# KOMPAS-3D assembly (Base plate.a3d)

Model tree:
1. X Axis
2. Y Axis
3. Z Axis
4. Origin
5. Linear Pattern:1  (labels: Instance ( 2, 1 );; Instance ( 3, 1 );; Instance ( 4, 1 );; Instance ( 5, 1 );)
     Included Angle = 90; N 2 = 1; Spacing 2 = 10; Orientation = 1; Distance = 60; Orientation = 1

Expressions: W_BP+(2*Delta); L_BP-100-(Delta*2)
Referenced files in C:\Work\01 К О М П А С\Модели примеры\2009_04_For_Poland_AXAPACK\My sample\Box_sample\: skrzynia1.a3d|L, skrzynia1.a3d|NR_Base, skrzynia1.a3d|W, Base plate.m3d, rail1.m3d
Referenced files in C:\Work\01 К О М П А С\Модели примеры\2009_04_For_Poland_AXAPACK\My sample\: skrzynia1.a3d
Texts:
  Three Point Plane
  Plane at Angle
  Line and Point Plane
  Axis through Two Vertices
  Axis of Feature
  Axis of Conical Surface
  Axis through Edge
  Trim by Surface
  Trim by Sketch
  Intersection Axis of Two Planes
  Two Line Plane
  Line and Face Plane
  Pattern by Sample
  Point in CM
  Feature with No History
  Linear Dimension from Line to Point
  Surface Finish Symbol
  Geometric Tolerance Symbol
  Leader #1
  Leader #2
  Leader #3
  Shape Deviations and Datum
  Node point number
  Mark of coordination axis
  Node point designation
  Mark/Reference designation with leader
  Mark/reference designation on line
  Mark/Reference designation without leader
  Instance ( 2, 1 );
  Instance ( 3, 1 );
  Instance ( 4, 1 );
  Instance ( 5, 1 );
